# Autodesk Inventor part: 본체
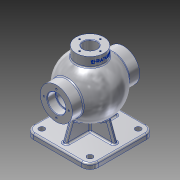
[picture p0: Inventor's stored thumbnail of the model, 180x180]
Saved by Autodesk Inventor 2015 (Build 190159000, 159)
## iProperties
Created: 2025-08
Part Number: 본체
Material: 알루미늄 6061
Document SubType Name: Modeling
Designer: user
Density: 2.7 g/cm^3
Appearance: 알루미늄 - 평지
Author: user
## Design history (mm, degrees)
sketch "스케치1"
  geometry: L1 (-46.5, 62.5)-(46.5, 62.5); L2 (62.5, 46.5)-(62.5, -46.5); L3 (46.5, -62.5)-(-46.5, -62.5); L4 (-62.5, -46.5)-(-62.5, 46.5); A1 r 16 centre (-46.5, 46.5) between (-46.5, 62.5) and (-62.5, 46.5); A2 r 16 centre (46.5, 46.5) between (62.5, 46.5) and (46.5, 62.5); A3 r 16 centre (46.5, -46.5) between (46.5, -62.5) and (62.5, -46.5); A4 r 16 centre (-46.5, -46.5) between (-62.5, -46.5) and (-46.5, -62.5); 4 further points
  constraints: 8 end point, 8 point on circle, 8 tangent, 6 point on line, 4 centre point, 2 parallel, 1 horizontal, 1 perpendicular
  dimensions: "d0" = 125 distance of point (-62.5, 62.5) point (62.5, 62.5); "d1" = 125 distance of point (62.5, 62.5) point (62.5, -62.5); "d2" = 62.5 distance from line of L1 point (0, 0); "d3" = 62.5 distance from line of L2 point (0, 0); "d4" = 16 radius of A1; "d5" = 16 radius of A2; "d6" = 16 radius of A3; "d7" = 16 radius of A4
extrude "돌출1" new body sketch "스케치1" distance "d8" = 10; taper "d9" = 0 deg
hole "구멍1" diameter "d12" = 11; stored, may be unused: countersink angle "d16" = 90 deg, drill point angle "d18" = 118 deg; dims "d10" = 16, "d11" = 16, "d13" = 6, "d14" = 4, "d15" = 2, "d17" = 8
sketch "스케치3"
  geometry: L1 (62.5, 10)-(62.5, 0) reference; L2 (62.5, 0)-(-62.5, 0) reference; L3 (-62.5, 0)-(-62.5, 10) reference; L4 (-62.5, 10)-(62.5, 10) reference; L5 (41, 10)-(52, 10) reference; L6 (50.5, 10)-(28.392, 70.741); L7 (28.392, 70.741)-(-28.392, 70.741); L8 (-28.392, 70.741)-(-50.5, 10); L9 (-46.5, 10)-(-62.5, 10) reference; 1 further point
  constraints: 6 end point, 2 point on line, 1 parallel
  dimensions: "d25" = 20 deg angle of L3 L8; "d26" = 20 deg angle of L1 L6; "d27" = 12 distance of L3.end L8.end; "d28" = 12 distance of L6.start L1.start; "d29" = 56.78418 distance of L6.end L7.end
extrude "돌출2" join sketch "스케치3" stored distance "d30" = 8; taper "d31" = 0 deg
sketch "스케치4"
  geometry: L1 (62.5, 10)-(62.5, 0) reference; L2 (62.5, 0)-(-62.5, 0) reference; L3 (-62.5, 0)-(-62.5, 10) reference; L4 (-62.5, 10)-(-4, 10) reference; L5 (-4, 10)-(-4, 70.741) reference; L6 (-4, 70.741)-(4, 70.741) reference; L7 (4, 70.741)-(4, 10) reference; L8 (4, 10)-(62.5, 10) reference; L9 (-52, 10)-(-41, 10) reference; L10 (-46.5, 10)-(-62.5, 10) reference; L11 (-50.5, 10)-(-29.534, 67.603); L12 (-29.534, 67.603)-(29.534, 67.603); L13 (29.534, 67.603)-(50.5, 10); L14 (62.5, 10)-(46.5, 10) reference; 1 further point
  constraints: 6 end point, 2 point on line, 1 parallel
  dimensions: "d32" = 12 distance of L11.start L3.end; "d33" = 12 distance of L1.start L13.end; "d34" = 20 deg angle of L1 L13; "d35" = 20 deg angle of L3 L11; "d36" = 59.06819 distance of L11.end L12.end
extrude "돌출3" join sketch "스케치4" stored distance "d37" = 8; taper "d38" = 0 deg
sketch "스케치6"
  geometry: L1 (0, 139)-(0, 31); L2 (-4, 10)-(-4, 67.603) reference; L3 (-46.5, 0)-(46.5, 0) reference; A1 r 54 centre (0, 85) between (0, 139) and (0, 31); A2 r 44 centre (0, 85) between (0, 129) and (0, 41); 3 further points
  constraints: 4 point on circle, 2 centre point, 2 coincident, 2 end point, 2 midpoint, 2 point on line, 1 parallel, 1 vertical alignment
  dimensions: "d42" = 108 diameter of A1; "d44" = 88 diameter of A2; "d50" = 85 distance from line of A1.centre L3
revolve "회전2" sketch "스케치6" stored, may be unused: angle "d45" = 90 deg
node "작업 평면1"
sketch "스케치8"
  geometry: C1 r 27 at (0, 0); 1 further point
  constraints: 1 centre point, 1 coincident
  dimensions: "d51" = 54 diameter of C1
extrude "돌출5" join sketch "스케치8" stored distance "d52" = 130; taper "d53" = 0 deg
node "작업 평면2"
sketch "스케치9"
  geometry: L1 (-46.5, 0)-(46.5, 0) reference; C1 r 31 at (0, 85); 2 further points
  constraints: 1 centre point, 1 midpoint, 1 vertical alignment
  dimensions: "d55" = 62 diameter of C1; "d56" = 85 distance from line of C1.centre L1
extrude "돌출6" join sketch "스케치9" distance "d57" = 130; taper "d58" = 0 deg
sketch "스케치10"
  geometry: L1 (27.526, 70.741)-(28.392, 70.741) reference; L2 (28.392, 70.741)-(33.559, 56.544) reference; L3 (-33.559, 56.544)-(-28.392, 70.741) reference; L4 (-28.392, 70.741)-(-27.526, 70.741) reference; L5 (-27, 150)-(27, 150) reference; L6 (27, 150)-(27, 131.765) reference; L7 (37.385, 46.034)-(50.5, 10) reference; L8 (50.5, 10)-(62.5, 10) reference; L9 (62.5, 10)-(62.5, 0) reference; L10 (62.5, 0)-(-62.5, 0) reference; L11 (-62.5, 0)-(-62.5, 10) reference; L12 (-62.5, 10)-(-50.5, 10) reference; L13 (-50.5, 10)-(-37.385, 46.034) reference; L14 (-27, 131.765)-(-27, 150) reference; L15 (-4, 41.365)-(-4, 54.259) reference; L16 (0, 129)-(0, 41); A1 r 31 centre (0, 85) between (27.526, 70.741) and (-27.526, 70.741) reference; A2 r 44 centre (0, 85) between (33.559, 56.544) and (0, 129) reference; A3 r 44 centre (0, 85) between (0, 129) and (-33.559, 56.544) reference; A4 r 54 centre (0, 85) between (37.385, 46.034) and (27, 131.765) reference; A5 r 54 centre (0, 85) between (-27, 131.765) and (-37.385, 46.034) reference; A6 r 44 centre (0, 85) between (0, 129) and (0, 41); 1 further point
  constraints: 3 end point, 3 point on circle, 1 centre point, 1 coincident, 1 vertical
  dimensions: "d60" = 88 distance of L16.start L16.end
revolve "회전3" sketch "스케치10" stored, may be unused: angle "d61" = 90 deg
hole "구멍2" diameter "d64" = 11; stored, may be unused: countersink angle "d68" = 90 deg, drill point angle "d70" = 118 deg; dims "d62" = 10, "d63" = 10, "d65" = 6, "d66" = 35, "d67" = 16, "d69" = 8
hole "구멍3" diameter "d73" = 30; stored, may be unused: countersink angle "d77" = 90 deg, drill point angle "d79" = 118 deg; dims "d71" = 10, "d72" = 10, "d74" = 6, "d75" = 35, "d76" = 16, "d78" = 8
hole "구멍4" diameter "d82" = 26; stored, may be unused: countersink angle "d86" = 90 deg, drill point angle "d88" = 0 deg; dims "d80" = 10, "d81" = 10, "d83" = 6, "d84" = 26, "d85" = 16, "d87" = 54
sketch "스케치11"
  geometry: L1 (0, 0)-(0, 24); C1 r 17.5 at (0, 0) reference; 1 further point
  constraints: 2 end point, 1 vertical
  dimensions: "d89" = 24 distance of L1.start L1.end
hole "구멍5" sketch "스케치11" at (0, 24) diameter "d90" = 3.242; stored, may be unused: countersink angle "d94" = 90 deg, drill point angle "d96" = 118 deg; dims "d91" = 12, "d92" = 26, "d93" = 16, "d95" = 15
sketch "스케치12"
  geometry: L1 (0, 0)-(0, 20)
  constraints: 2 end point, 1 vertical
  dimensions: "d100" = 20 distance of L1.start L1.end
hole "구멍6" sketch "스케치12" at (0, 20) diameter "d101" = 3.242; stored, may be unused: countersink angle "d105" = 90 deg, drill point angle "d107" = 118 deg; dims "d102" = 9, "d103" = 26, "d104" = 16, "d106" = 11
fillet "모깎기1" dims "d111" = 0.6
chamfer "모따기1" distance "d112" = 1; stored, may be unused: second distance "d113" = 2, angle "d114" = 45 deg
chamfer "모따기2" distance "d115" = 1; stored, may be unused: second distance "d116" = 2, angle "d117" = 45 deg
fillet "모깎기2" dims "d118" = 3
fillet "모깎기3" dims "d119" = 3
fillet "모깎기4" dims "d120" = 3
fillet "모깎기5" dims "d121" = 3
sketch "스케치13"
  geometry: L1 (18.379, 150)-(21.621, 150) reference; 2 further points
  constraints: 1 vertical alignment, 1 other
  dimensions: "d122" = 9 distance from line of point (0, 141) L1
feature "엠보싱1" sketch "스케치13" dims "d0" = 125, "d1" = 125, "d2" = 62.5, "d3" = 62.5, "d4" = 16, "d5" = 16, "d6" = 16, "d7" = 16, "d123" = 0.5, "d124" = 0
sketch "스케치14"
  geometry: 1 further point
node "솔리드1"
pattern_linear "직사각형 패턴1" dims "d21" = 93, "d24" = 93
pattern_circular "원형 패턴1" dims angle "d98" = 360 deg
mirror "대칭1"
pattern_circular "원형 패턴2" dims angle "d109" = 360 deg
node "절단 모서리 투영1"
node "절단 모서리 투영2"
node "절단 모서리 투영5"
other parameters: "d54" = -65
